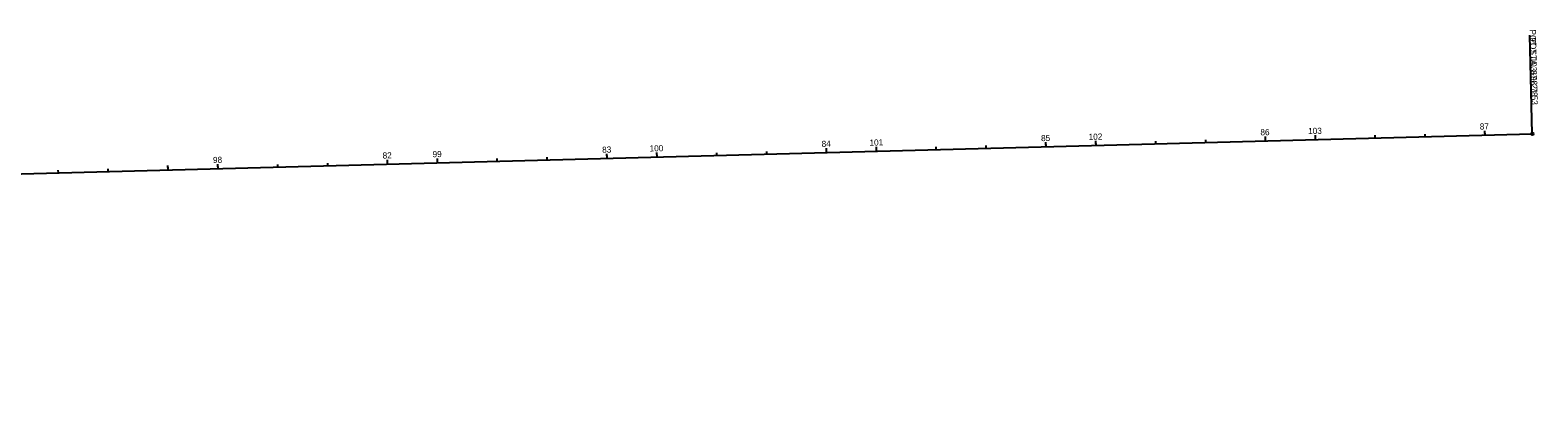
# Model space of a CAD drawing. Extents: x 2402033 to 2407434, y 498266 to 500417.
# Drawn here: x 2406748 to 2407434, y 498666 to 498830 of the extents above; entities that cross this region are included whole.
import ezdxf

# ---------------------------------------------------------------- set-up
doc = ezdxf.new("R2010")
doc.units = 0
for name, color, linetype in [('DR_P_Ditch', 7, 'Continuous'), ('GK_Drainage_Nodes', 7, 'Continuous'), ('PV_P_EOP', 7, 'Continuous'), ('PV_P_Shoulder', 7, 'Continuous'), ('RD_P_GR_Lt', 7, 'Continuous'), ('RD_P_GR_Rt', 7, 'Continuous'), ('SN_X_Public', 7, 'Continuous')]:
    doc.layers.add(name, color=color, linetype=linetype)

msp = doc.modelspace()

# ---------------------------------------------------------------- linework, layer by layer
at = {"layer": 'DR_P_Ditch'}
msp.add_line((2407431.7, 498783.04), (2407430.51, 498828.02), dxfattribs=at)
msp.add_line((2407431.7, 498783.04), (2407430.51, 498828.02), dxfattribs=at)
msp.add_circle((2407431.7, 498783.04), 0.6, dxfattribs=at)
msp.add_circle((2407431.7, 498783.04), 0.6, dxfattribs=at)
at = {"layer": 'GK_Drainage_Nodes'}
msp.add_line((2407431.7, 498783.04), (2407430.51, 498828.02), dxfattribs=at)
msp.add_line((2407431.7, 498783.04), (2407430.51, 498828.02), dxfattribs=at)
msp.add_circle((2407431.7, 498783.04), 0.6, dxfattribs=at)
msp.add_circle((2407431.7, 498783.04), 0.6, dxfattribs=at)
at = {"layer": 'PV_P_EOP'}
msp.add_line((2403004.47, 498665.82), (2407431.7, 498783.04), dxfattribs=at)
at = {"layer": 'PV_P_Shoulder'}
for p, q in [((2407210.25, 498777.17), (2407210.19, 498779.17)), ((2407232.99, 498777.77), (2407232.96, 498778.97)), ((2407310.21, 498779.82), (2407310.18, 498781.02)), ((2407332.96, 498780.42), (2407332.92, 498781.62)), ((2407410.18, 498782.47), (2407410.14, 498783.66)), ((2407010.32, 498771.88), (2407010.28, 498773.08)), ((2407033.06, 498772.48), (2407033.01, 498774.48)), ((2407110.28, 498774.53), (2407110.25, 498775.72)), ((2407133.03, 498775.13), (2407132.99, 498776.33)), ((2406810.39, 498766.59), (2406810.35, 498767.78)), ((2406833.13, 498767.19), (2406833.1, 498768.39)), ((2406910.35, 498769.23), (2406910.32, 498770.43)), ((2406933.1, 498769.83), (2406933.06, 498771.03))]:
    msp.add_line(p, q, dxfattribs=at)
at = {"layer": 'RD_P_GR_Lt'}
for p, q in [((2407210.25, 498777.17), (2407210.19, 498779.17)), ((2407232.99, 498777.77), (2407232.94, 498779.77)), ((2407260.23, 498778.5), (2407260.2, 498779.69)), ((2407282.97, 498779.1), (2407282.94, 498780.3)), ((2407310.21, 498779.82), (2407310.16, 498781.82)), ((2407332.96, 498780.42), (2407332.9, 498782.42)), ((2407360.19, 498781.14), (2407360.16, 498782.34)), ((2407382.94, 498781.74), (2407382.91, 498782.94)), ((2407410.18, 498782.47), (2407410.12, 498784.46)), ((2406933.1, 498769.83), (2406933.04, 498771.83)), ((2406960.33, 498770.56), (2406960.3, 498771.75)), ((2406983.08, 498771.16), (2406983.05, 498772.36)), ((2407010.32, 498771.88), (2407010.26, 498773.88)), ((2407033.06, 498772.48), (2407033.01, 498774.48)), ((2407060.3, 498773.2), (2407060.27, 498774.4)), ((2407083.04, 498773.8), (2407083.01, 498775)), ((2407110.28, 498774.53), (2407110.23, 498776.52)), ((2407133.03, 498775.13), (2407132.97, 498777.13)), ((2407160.26, 498775.85), (2407160.23, 498777.05)), ((2407183.01, 498776.45), (2407182.98, 498777.65)), ((2406760.4, 498765.26), (2406760.37, 498766.46)), ((2406783.15, 498765.86), (2406783.12, 498767.06)), ((2406810.39, 498766.59), (2406810.33, 498768.58)), ((2406833.13, 498767.19), (2406833.08, 498769.19)), ((2406860.37, 498767.91), (2406860.34, 498769.11)), ((2406883.11, 498768.51), (2406883.08, 498769.71)), ((2406910.35, 498769.23), (2406910.3, 498771.23))]:
    msp.add_line(p, q, dxfattribs=at)
at = {"layer": 'RD_P_GR_Rt'}
msp.add_line((2407431.7, 498783.04), (2407430.51, 498828.02), dxfattribs=at)
msp.add_circle((2407431.7, 498783.04), 0.6, dxfattribs=at)
at = {"layer": 'SN_X_Public'}
for p, q in [((2407210.25, 498777.17), (2407210.21, 498778.37)), ((2407033.06, 498772.48), (2407033.01, 498774.48))]:
    msp.add_line(p, q, dxfattribs=at)

# ---------------------------------------------------------------- texts
at = {"layer": 'DR_P_Ditch'}
for s, p in [('POT', (2407430.49, 498830.54)), ('POT', (2407430.58, 498826.9)), (' STA. ', (2407430.7, 498822.5)), ('103+98.78', (2407430.82, 498817.77)), ('87+21.53', (2407430.98, 498811.93))]:
    msp.add_text(s, height=2.8, rotation=271.5166, dxfattribs=at).set_placement(p)
at = {"layer": 'GK_Drainage_Nodes'}
for s, p in [('POT', (2407430.49, 498830.54)), ('POT', (2407430.58, 498826.9)), (' STA. ', (2407430.7, 498822.5)), ('103+98.78', (2407430.82, 498817.77)), ('87+21.53', (2407430.98, 498811.93))]:
    msp.add_text(s, height=2.8, rotation=271.5166, dxfattribs=at).set_placement(p)
at = {"layer": 'PV_P_Shoulder'}
for s, p in [('85', (2407207.99, 498779.66)), ('100', (2407029.71, 498774.94))]:
    msp.add_text(s, height=2.8, rotation=1.5166, dxfattribs=at).set_placement(p)
at = {"layer": 'RD_P_GR_Lt'}
for s, p in [('86', (2407307.9, 498782.3)), ('103', (2407329.63, 498782.88)), ('87', (2407407.81, 498784.95)), ('84', (2407108.06, 498777.01)), ('101', (2407129.85, 498777.59)), ('85', (2407207.99, 498779.66)), ('102', (2407229.65, 498780.23)), ('98', (2406830.87, 498769.68)), ('82', (2406908.12, 498771.72)), ('99', (2406930.86, 498772.32)), ('83', (2407008.1, 498774.36)), ('100', (2407029.71, 498774.94))]:
    msp.add_text(s, height=2.8, rotation=1.5166, dxfattribs=at).set_placement(p)
at = {"layer": 'RD_P_GR_Rt'}
for s, p in [('POT', (2407430.58, 498826.9)), ('103+98.78', (2407430.82, 498817.77))]:
    msp.add_text(s, height=2.8, rotation=271.5166, dxfattribs=at).set_placement(p)
at = {"layer": 'SN_X_Public'}
msp.add_text('100', height=2.8, rotation=1.5166, dxfattribs=at).set_placement((2407029.71, 498774.94))

doc.saveas('drawing.dxf')
